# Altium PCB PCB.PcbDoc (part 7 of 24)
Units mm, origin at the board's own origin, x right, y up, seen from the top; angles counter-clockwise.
Board outline 100 x 160 mm, 10 copper layers (TOP_L1, L2, L3, L4, L5, L6, L7, L8, L9, BOTTOM_L10), stack 1.946 mm thick; 1358 components, 1149 nets, 6777 pads, 10914 vias.
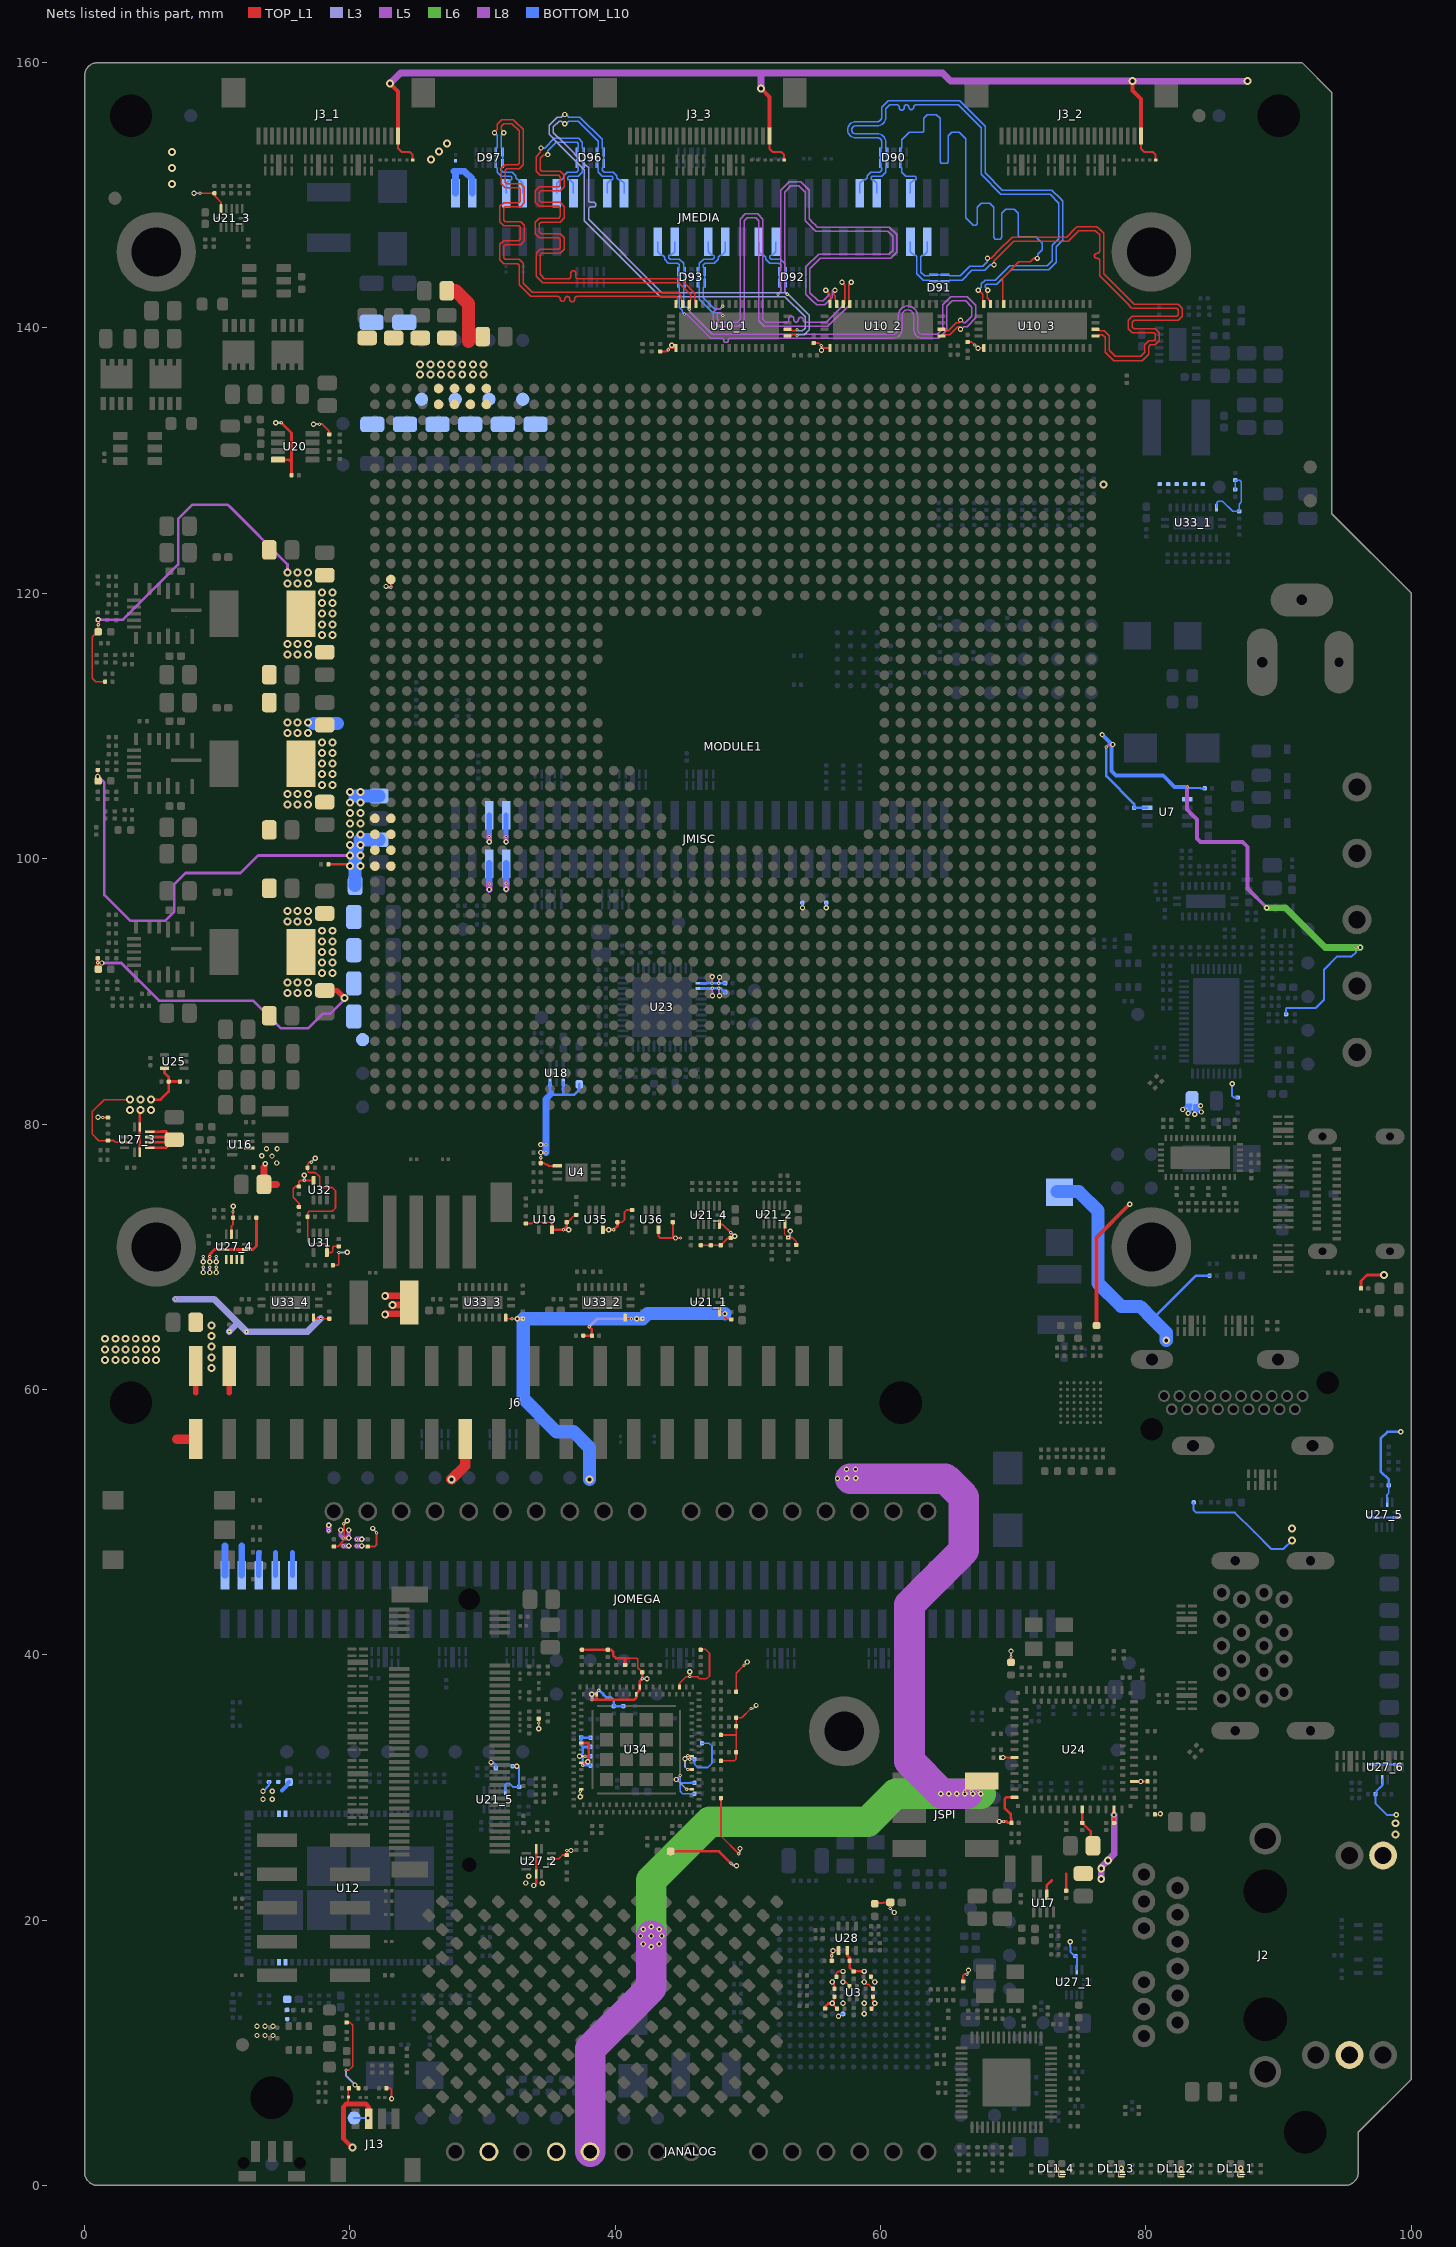
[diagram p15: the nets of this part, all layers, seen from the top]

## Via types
v1: diameter 0.25, hole 0.1, TOP_L1 to L2, tented both sides, 3439 vias
v2: diameter 0.25, hole 0.1, L2 to L3, tented both sides, 2256 vias
v3: diameter 0.25, hole 0.1, L9 to BOTTOM_L10, tented both sides, 1685 vias
v4: diameter 0.25, hole 0.1, L8 to L9, tented both sides, 1675 vias
v5: diameter 0.4, hole 0.2, L3 to L8, tented both sides, 1251 vias
v6: diameter 0.6, hole 0.3, TOP_L1 to BOTTOM_L10, tented both sides, 600 vias
v7: diameter 0.24, hole 0.1, TOP_L1 to L2, tented both sides, 8 vias

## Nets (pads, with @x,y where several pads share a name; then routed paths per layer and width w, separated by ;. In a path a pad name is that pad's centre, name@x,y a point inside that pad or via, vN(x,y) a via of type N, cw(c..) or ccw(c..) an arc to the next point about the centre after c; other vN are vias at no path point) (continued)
+3V3: C38.2 C39.2 C62.2 C69_1.2 C69_2.2 C69_3.2 C80.2 C81.2 C82.2 C83.2 C91.2 C92.1 C93.1 C94.2 C101.2 C115.2 C117.2 C118.2 C122.2 C123.2 C128.2 C129.2 C130.2 C131.2 C132.1 C133.1 C137.2 C140.1 C141.1 C142.1 C143.1 C148.1 C149.1 C174_1.2 C175_2.2 C175_3.2 C175_4.2 C175_5.2 C177.2 C178.2 C179_1.2 C179_2.2 C179_3.2 C179_4.2 C179_5.2 C179_6.2 C202.2 C203.2 C204.2 C206.2 C207.2 C208.2 C228.2 C229.2 C230.2 C231.2 C232.2 C233.2 C234.2 C235.2 C236.2 C237.2 C238.2 C249.2 C250.2 C251.2 C252.2 C258.2 C259.1 C260.2 C262.2 C263.2 C265.2 C266.2 C267.2 C268.2 C269.2 C272.2 C273.2 C274.2 C275.2 C278.2 C300.2 C306.2 C312.2 C313.2 C315.2 C316.2 C317.2 C318.2 C338.2 D15_1.2 D15_2.2 D15_3.2 D85.2 DL1_1.1 DL1_2.1 DL1_3.1 DL1_4.1 J2.14 J2.16 J3_1.22 J3_2.22 J3_3.22 JMEDIA.58 JMEDIA.60 JMISC.53 JMISC.55 JOMEGA.91 JOMEGA.93 JOMEGA.95 L3.2 L4.2 L6.1 L16.1 L18.2 L19.1 MODULE1.A16 MODULE1.A17 MODULE1.A18 MODULE1.A19 MODULE1.B16 MODULE1.B17 MODULE1.B18 MODULE1.B19 MODULE1.B34 MODULE1.E45 MODULE1.E46 MODULE1.F45 MODULE1.F46 MODULE1.G45 MODULE1.G46 MODULE1.H45 MODULE1.H46 R6.2 R7.2 R105.2 R118.1 R124.1 R136.2 R138.2 R155.1 R158.1 R159.1 R160.1 R164.1 R175.1 R176.1 R177.1 R181.2 R191.2 R210.2 R211.2 R220.2 R233.1 R261.2 R275.1 R286.2 R287.2 R295.2 R296.2 R297.2 R298.2 R303.2 R304.2 R317.2 R327.1 R328.1 R329.1 R337.1 R371.2 R372.2 R373.2 R374.2 R375.2 R376.2 R420.1 R431.1 R432.1 R434.1 R435.1 R455.2 R463.1 R464.1 R475.2 R487.2 R489.1 TP74.X TP75.X TP76.X TP77.X TP91.X U3.F7 U3.F9 U3.G6 U3.G7 U3.G9 U3.G10 U3.J6 U3.J7 U3.J9 U3.J10 U3.K7 U3.K9 U4.1 U7.5 U10_1.1 U10_2.1 U10_3.1 U12.4 U12.5 U12.72 U12.73 U16.2 U17.2 U18.4 U18.6 U19.5 U20.4 U21_2.11 U21_3.11 U21_4.11 U21_5.11 U24.A3 U24.A34 U24.A39 U24.A47 U24.A51 U25.5 U27_1.3 U27_2.3 U27_2.6 U27_2.11 U27_3.3 U27_3.6 U27_3.11 U27_4.3 U27_5.3 U27_6.3 U28.4 U28.5 U32.5 U33_1.19 U34.AP18 U34.AP30 U34.AR19 U34.AR31 U34.F2 U34.F34 U34.M2 U34.P34 U34.T2 U34.T34 U34.Y34 U35.5 U36.5 | length 454.3
  TOP_L1 w0.084: U21_2.11@52.789,72.469 52.789,71.69 C175_2.2@53.039,71.44
  TOP_L1 w0.1: R420.1@1.025,117.1 0.991,117.1 0.751,116.86 0.741,116.86 0.572,116.691 0.572,113.597 0.829,113.34 R124.1@1.55,113.34 ; 40.736,39.735 41.619,39.735 41.706,39.647 41.706,39.004 R136.2@42.036,38.674
  TOP_L1 w0.127: C80.2@1,106.69 C80.2@1,106.69 v5(1.002,106.191) v5(1.002,106.191) 1.013,106.18 1.013,105.877 R118.1@1.025,105.865 ; v2(1.377,80.494) R337.1@1.765,80.494 R337.1@1.771,80.5 ; U27_3.3@3.015,78.619 2.341,78.619 2.21,78.75 1.771,78.75 C179_3.2@1.765,78.744 1.079,78.744 0.582,79.241 0.582,80.941 1.479,81.837 v6(3.414,81.837) ; v1(8.7,150.15) C175_3.2@9.786,150.15 9.845,150.091 9.845,149.916 10.286,149.474 U21_3.11@10.286,148.975 ; U27_4.3@11.068,71.686 11.068,72.314 11.193,72.439 C179_4.2@11.193,72.936 v2(11.193,73.385) ; R455.2@16.16,73.75 16.16,74.038 15.722,74.476 15.722,75.13 15.877,75.285 C306.2@16.16,75.285 ; R261.2@18.71,69.35 19.09,69.35 19.164,69.424 v1(19.164,70.312) ; v2(19.709,8.68) 19.729,8.701 19.934,8.701 20.214,8.981 20.214,12.068 20.007,12.275 R317.2@19.75,12.275 ; R489.1@33.266,72.498 33.698,72.498 33.8,72.6 35.13,72.6 35.232,72.499 U19.5@35.232,72.033 ; v1(34.223,34.849) R296.2@34.223,35.175 ; U27_2.3@35.191,24.624 35.75,24.624 36.025,24.899 C179_2.2@36.341,24.899 v1(36.341,25.241) ; C94.2@36.332,72.598 36.413,72.679 36.491,72.679 36.879,73.067 36.981,73.067 R431.1@37.062,73.148 ; v1(37.35,29.7) 37.421,29.771 U34.F34@37.421,29.849 ; C101.2@40.162,72.598 40.509,72.598 40.692,72.781 40.692,73.364 40.841,73.513 R432.1@41.262,73.513 ; U34.AR31@44.841,37.569 44.841,37.844 45.326,38.328 45.596,38.328 v2(45.62,38.353) ; v1(45.375,29.849) U34.F2@45.761,29.849 ; v1(45.453,32.405) 45.453,32.383 45.486,32.349 U34.T2@45.761,32.349 ; v2(45.457,31.343) 45.46,31.346 45.758,31.346 U34.M2@45.761,31.349 ; C231.2@45.614,38.674 45.617,38.671 45.617,38.355 v2(45.62,38.353) ; R210.2@46.436,40.374 46.462,40.4 46.8,40.4 47.1,40.1 47.1,38.4 46.88,38.18 46.352,38.18 46.204,38.328 45.644,38.328 v2(45.62,38.353) ; R329.1@46.45,70.862 R327.1@47.95,70.862 47.956,70.862 48.057,70.963 48.057,70.969 48.487,71.399 48.687,71.399 C175_4.2@48.7,71.412 ; R6.2@47.961,29.199 47.961,26.339 v1(49.3,25) ; R7.2@47.961,31.999 48.988,31.999 49.1,32.111 49.1,32.638 R211.2@49.111,32.649 49.111,33.949 ; R304.2@47.961,33.949 49.111,33.949 ; R297.2@49.111,37.199 49.111,38.611 v1(49.7,39.2) ; v1(50.224,35.942) 49.531,35.249 R286.2@49.111,35.249 R298.2@49.111,34.599 49.111,33.949 ; C175_2.2@53.039,71.44 53.039,71.444 v1(53.043,71.448) ; C175_2.2@53.048,71.448 53.335,71.448 53.639,71.145 R181.2@53.639,70.89 ; C69_2.2@54.951,138.859 55.339,138.859 v1(55.523,138.675) 55.707,138.491 U10_2.1@56.182,138.491 ; v5(56.363,15.329) 56.363,15.311 56.513,15.161 C268.2@56.513,14.829 ; C260.2@56.513,14.229 56.513,13.897 56.363,13.747 v2(56.363,13.729) 56.363,13.696 56.502,13.557 56.502,13.54 C263.2@56.713,13.329 ; C266.2@56.663,15.729 56.663,16.013 56.779,16.129 v2(57.163,16.129) ; v4(57.163,15.329) 57.187,15.305 57.387,15.305 C269.2@57.663,15.029 ; v4(58.763,15.329) 58.93,15.162 59.08,15.162 C273.2@59.413,14.829 ; C275.2@59.263,15.729 59.263,15.629 v2(59.563,15.329) ; C272.2@59.313,13.329 59.313,13.344 59.54,13.57 59.54,13.705 v5(59.563,13.729) 59.563,13.747 59.413,13.897 C262.2@59.413,14.229 ; L6.1@59.563,21.229 59.626,21.292 60.173,21.292 60.21,21.329 C259.1@60.728,21.329 60.728,20.87 v1(60.724,20.866) ; C69_3.2@66.551,138.934 66.875,138.934 v1(67.096,138.713) 67.318,138.491 U10_3.1@67.782,138.491 ; L18.2@69.826,39.424 v1(69.826,39.871)
  TOP_L1 w0.15: C306.2@16.16,75.3 16.16,75.662 16.248,75.75 v1(16.564,75.75) U32.5@17.26,75.75 ; v2(17.7,132.75) 17.707,132.743 17.925,132.743 18.439,132.229 R233.1@18.439,131.974 ; R372.2@18.796,48.15 19.066,48.15 19.543,48.627 v2(19.543,49.863) ; v5(20.387,7.568) 20.41,7.568 20.619,7.359 R375.2@20.641,7.359 ; R371.2@21.336,48.15 21.868,48.15 22,48.282 v2(22,49.2) ; R376.2@22.741,7.324 23.018,7.324 23.135,7.207 23.135,6.538 v1(23.145,6.528) ; J3_1.22@23.624,154.475 23.624,153.557 23.921,153.26 24.524,153.26 24.724,153.06 D15_1.2@24.724,152.66 ; v5(34.382,77.849) v2(34.382,77.449) R220.2@34.382,77.049 34.644,77.049 34.744,76.949 34.871,76.949 34.971,76.849 U4.1@35.632,76.849 ; U36.5@43.262,72.033 43.262,71.532 43.394,71.4 44.342,71.4 ; C69_1.2@43.382,138.236 43.855,138.236 v2(43.983,138.363) 44.11,138.491 U10_1.1@44.582,138.491 ; 44.342,71.396 44.342,71.4 ; C278.2@44.342,72.598 44.342,71.4 ; v1@44.923,71.408 v1(44.919,71.403) 44.915,71.4 44.342,71.4 ; U21_4.11@47.85,72.441 48.075,72.441 v2(48.694,71.822) 48.697,71.819 48.697,71.415 C175_4.2@48.7,71.412 ; J3_3.22@51.624,154.475 51.624,153.498 51.863,153.26 52.524,153.26 52.724,153.06 D15_3.2@52.724,152.66 ; C265.2@56.313,16.929 v2(56.313,17.309) 56.313,17.513 56.509,17.709 U28.4@56.833,17.709 ; R434.1@66.213,15.379 66.213,15.829 66.313,15.929 66.493,15.929 v2(66.51,15.912) ; C204.2@69.066,32.249 69.068,32.25 69.224,32.25 v5(69.225,32.251) v5(69.225,32.251) 70.09,32.25 U24.A34@70.091,32.249 ; U24.A3@79.091,30.449 v5(79.604,30.449) C206.2@80.116,30.449 ; J3_2.22@79.624,154.475 79.624,153.498 79.863,153.26 80.524,153.26 80.724,153.06 D15_2.2@80.724,152.66 ; R191.2@80.666,27.959 81.021,27.959 81.063,28.001 v1(81.09,28.001)
  TOP_L1 w0.18: MODULE1.B34@23.082,121.036 23.1,121.018 v1(23.1,120.45) ; U24.A47@75.191,28.349 75.191,27.924 75.189,27.922 75.189,27.389 75.191,27.387 C207.2@75.191,27.324 75.818,26.698 75.829,26.698 75.829,25.771 C208.2@76.003,25.597
  TOP_L1 w0.2: C91.2@1,117.99 1.025,117.965 v2(1.025,117.621) R420.1@1.025,117.1 ; U27_3.6@4.165,77.869 U27_3.11@4.165,79.769 4.165,81.067 v6(4.214,81.067) ; v6(5.014,81.837) 5.737,81.837 6.34,82.44 C338.2@6.34,83.202 ; U25.5@6.025,84.202 6.025,83.852 6.34,83.537 C338.2@6.34,83.202 ; R487.2@7.19,83.202 C338.2@6.34,83.202 ; U20.4@14.574,130.074 15.369,130.074 15.599,129.844 ; v1(14.824,132.85) 15.599,132.075 15.599,129.844 ; C300.2@15.599,128.899 15.599,129.844 ; C251.2@18.375,99.566 19.699,99.566 cw(c19.699,99.123) v6(20.012,99.436) ; 34.041,22.793 U27_2.11@34.041,23.474 U27_2.6@34.041,25.374 ; U19.5@35.232,72.033 v2(36.097,72.033) 36.332,72.267 C94.2@36.332,72.598 ; U34.P34@37.421,31.849 37.84,31.849 37.919,31.928 v1(37.933,31.928) 37.933,31.942 38,32.009 38,32.349 ; U34.T34@37.421,32.349 v2(37.711,32.349) 38,32.349 ; U34.Y34@37.421,33.349 38,33.349 38,32.349 ; R295.2@37.486,40.374 R287.2@39.436,40.374 39.675,40.374 39.844,40.205 39.844,39.948 40.057,39.735 40.736,39.735 R303.2@40.736,39.224 ; v1(38.241,36.595) 38.541,36.595 ; U34.AP30@38.591,37.019 38.591,36.646 38.541,36.595 ; U35.5@39.062,72.033 v2(39.873,72.033) 40.162,72.322 C101.2@40.162,72.598 ; U34.AP18@41.591,37.019 41.591,36.771 41.416,36.595 38.541,36.595 ; U34.AP18@41.591,37.094 41.841,37.344 U34.AR19@41.841,37.569 41.841,37.996 v1(42.036,38.191) R136.2@42.036,38.674 ; L19.1@44.173,25.175 47.823,25.175 v2(48.726,24.272) ; R435.1@55.813,13.329 55.813,13.474 56.068,13.729 v2(56.363,13.729) ; U28.5@57.483,17.709 57.483,17.326 57.663,17.146 C274.2@57.663,16.929 57.663,16.429 C267.2@57.963,16.129 v5(58.763,16.129) ; v1(69.278,27.436) 69.287,27.426 69.499,27.426 69.601,27.324 69.801,27.324 69.856,27.379 69.856,27.665 69.797,27.724 69.797,28.007 69.341,28.463 69.341,29.132 69.459,29.249 U24.A39@70.091,29.249 ; U17.2@72.531,21.909 72.531,22.631 72.9,23 ; v5(73.25,1.264) 73.25,1.257 73.645,0.862 DL1_4.1@73.645,0.855 ; C123.2@73.981,22.209 73.981,23.5 ; C202.2@77.591,27.324 v5(77.591,27.924) U24.A51@77.591,28.349 ; v2(78.147,0.855) v2(78.147,0.855) ; v2(82.645,0.844) DL1_2.1@82.645,0.855 ; v2(87.14,0.855) DL1_1.1@87.145,0.855 ; R105.2@96.201,67.609 96.201,68.151 96.664,68.614 v6(97.921,68.614)
  TOP_L1 w0.3: v6(23.026,158.424) 23.624,157.826 J3_1.22@23.624,154.475 ; v6(50.975,158.041) 51.002,158.041 51.624,157.418 J3_3.22@51.624,154.475 ; L16.1@76.275,64.81 76.275,71.458 v5(78.768,73.952) ; v6(78.981,158.609) 78.981,157.889 79.624,157.245 J3_2.22@79.624,154.475
  TOP_L1 w0.5: C117.2@13.518,75.441 13.518,76.75 ; C117.2@13.519,75.44 14.461,75.44
  TOP_L1 w1: C177.2@27.3,142.8 27.96,142.8 28.936,141.824 28.936,138.988
  L5 w0.5: v6(23.026,158.424) 23.815,159.212 50.984,159.212 ; v6(50.975,158.041) 50.984,158.051 50.984,159.212 ; v6(76.626,23.1) v6(76.626,23.9) 76.646,23.919 76.646,24.019 v6(77.126,24.5) 77.6,24.973 77.6,27.915 v5(77.591,27.924) ; v6(87.65,158.597) 87.644,158.603 78.986,158.603 v6(78.981,158.609) 65.271,158.609 64.667,159.212 50.984,159.212
  L6 w0.5: v5(89.1,96.3) 90.511,96.3 93.511,93.3 v5(96.15,93.3)
  L3 w0.127: v5(1.01,80.5) 1.013,80.497 1.374,80.497 v2(1.377,80.494) ; v5(8.25,150.15) v1(8.7,150.15) ; v2(11.193,73.385) 11.196,73.388 11.196,73.788 v5(11.199,73.791) ; v5(34.223,34.423) v1(34.223,34.849) ; v1(36.341,25.241) v5(36.659,25.241) ; v5(37.348,29.305) 37.35,29.308 v1(37.35,29.7) ; v5(44.6,30.6) 44.612,30.6 45.363,29.849 v1(45.375,29.849) ; v1(45.453,32.405) 45.453,32.384 45.259,32.19 v5(45.259,32.169) 45.259,31.541 v2(45.457,31.343) ; v2(45.62,38.353) v5(45.62,38.72) ; v1(49.3,25) 49.3,25.033 49.395,25.128 v5(49.395,25.391) ; v1(49.7,39.2) 49.95,39.45 v5(49.954,39.45) ; v1(50.224,35.942) 50.375,35.942 v5(50.611,36.178) ; v1(53.043,71.448) 53.043,71.482 53.178,71.616 v5(53.178,71.929) ; v1(55.523,138.675) 55.532,138.666 55.532,138.335 v5(55.542,138.326) ; v1(60.724,20.866) 61.02,20.57 v5(61.032,20.57) ; v1(67.096,138.713) 67.334,138.475 v5(67.334,138.469) ; v1(69.826,39.871) v5(69.826,40.274)
  L3 w0.15: v1(16.564,75.75) v5(16.564,76.142) ; v5(17.25,132.75) v2(17.7,132.75) ; v1(19.164,70.312) 19.168,70.308 19.772,70.308 v5(19.786,70.323) ; v2(19.543,49.863) 19.553,49.863 19.79,50.1 v5(19.8,50.1) ; v2(19.709,8.68) 19.709,8.246 v5(20.387,7.568) ; v5(21.719,49.519) 21.719,49.5 22,49.219 v2(22,49.2) ; v2(34.382,77.449) v5(34.382,77.849) ; v2(43.983,138.363) 43.983,138.39 44.256,138.663 v5(44.256,138.706) ; v5(44.54,71.412) 44.544,71.408 44.914,71.408 v1(44.919,71.403) ; v2(48.694,71.822) 48.708,71.822 48.99,71.54 v5(49.004,71.54) ; v2(56.313,17.309) 56.323,17.319 56.323,17.534 56.409,17.62 v5(56.409,17.688) ; v2(66.51,15.912) 66.51,15.939 66.574,16.003 66.574,16.181 v5(66.622,16.229) ; v5(81.086,28.003) 81.088,28.001 v1(81.09,28.001)
  L3 w0.18: v5(22.718,120.518) 22.764,120.518 22.832,120.45 v1(23.1,120.45)
  L3 w0.2: v5(1.023,118.019) 1.025,118.017 v2(1.025,117.621) ; v5(14.419,132.85) v1(14.824,132.85) ; v2(36.097,72.033) 36.099,72.032 36.486,72.032 v5(36.487,72.031) ; v4(37.307,32.349) v2(37.711,32.349) ; v1(37.933,31.928) v5(37.933,31.935) ; v5(38.233,37.018) 38.241,37.01 v1(38.241,36.595) ; v5(39.508,72.033) v2(39.873,72.033) ; v1(42.036,38.191) 42.037,38.19 v5(42.393,38.189) v5(42.393,38.189) ; v2(48.726,24.272) 48.74,24.272 48.878,24.134 49.102,24.134 v5(49.141,24.095) ; v5(68.936,27.427) 68.94,27.431 69.273,27.431 v1(69.278,27.436) ; v2(78.147,0.855) v5(78.147,1.287) ; v2(82.645,0.844) v5(82.645,1.266) ; v2(87.14,0.855) v5(87.14,1.3)
  L8 w0.127: v5(44.6,30.6) v4(44.9,30.9) ; v5(45.259,32.169) 45.277,32.151 45.59,32.151 v4(45.608,32.132) ; v4(95.833,93.321) 95.843,93.31 96.14,93.31 v5(96.15,93.3)
  L8 w0.15: v5(34.382,77.849) 34.762,77.849 v4(34.773,77.838) ; v5(34.382,78.449) 34.762,78.449 v3(34.773,78.438)
  L8 w0.2: v5(1.002,106.191) 1.029,106.191 1.489,105.73 1.489,97.264 3.43,95.323 6.088,95.323 6.755,95.99 6.755,98.06 7.608,98.914 11.745,98.914 13.068,100.236 v6(20.012,100.236) ; v5(1.023,118.019) 2.901,118.019 7.055,122.173 7.055,125.588 8.151,126.684 10.784,126.684 11.055,126.414 15.289,122.18 v6(15.289,121.554) ; v4(37.553,31.664) 37.785,31.897 37.895,31.897 v5(37.933,31.935) ; v5(38.233,37.018) 38.271,37.056 38.496,37.056 v4(38.763,37.323)
  L8 w0.3: v5(19.3,49.4) 19.3,49 v4(19.5,48.8) ; v5(19.9,48.8) v5(19.9,49.4) ; v3(83.103,105.4) 83.103,103.695 83.848,102.95 83.848,101.518 84.111,101.255 87.28,101.255 87.638,100.897 87.638,97.762 v5(89.1,96.3)
  L8 w0.4: v4(18.395,49.348) v5(18.395,49.748) ; v4(19.5,48.2) v5(19.9,48.2) ; v4(19.5,48.8) v5(19.9,48.8) ; v4(20.5,48.2) v5(20.9,48.2) ; v4(20.5,48.7) v5(20.9,48.7)
  L8 w0.5: v5(30.499,97.672) v4(30.499,98.091) ; v5(31.769,97.683) v4(31.769,98.134)
  BOTTOM_L10 w0.109: v5(54.109,96.3) R373.2@54.109,96.678 ; v5(55.899,96.3) R374.2@55.899,96.678
  BOTTOM_L10 w0.127: v4(44.9,30.9) 44.9,30.3 ; v4(45.608,32.132) C234.2@45.98,32.132 45.98,31.72 46.2,31.5 46.967,31.5 47.284,31.817 47.284,33.116 47.068,33.332 R138.2@46.53,33.332 ; C232.2@45.98,29.532 45.068,29.532 44.9,29.7 44.9,30.3 ; C233.2@45.98,30.332 44.932,30.332 44.9,30.3 ; U33_1.19@85.325,126.45 85.325,126.835 85.437,126.946 85.76,126.946 86.531,126.175 R155.1@87.025,126.175 87.025,126.715 87.188,126.878 87.188,128.412 87.075,128.525 C174_1.2@86.725,128.525 R158.1@86.725,127.825 ; U27_5.3@98.171,51.496 98.171,52.055 98.298,52.182 C179_5.2@98.298,52.771
  BOTTOM_L10 w0.15: v5(13.453,29.704) 13.9,30.151 C130.2@13.9,30.41 ; TP91.X@20.32,5.08 v5(21.36,5.08) ; v4(30.635,31.882) 30.654,31.863 30.837,31.863 31,31.7 R463.1@31,31.445 ; U21_5.11@31.7,29.77 31.7,30.173 31.832,30.305 32.018,30.305 32.278,30.045 C175_5.2@32.75,30.045 32.75,31.463 32.739,31.463 32.607,31.595 v3@32.573,31.595 ; R464.1@32.25,31.595 32.254,31.599 32.569,31.599 v5(32.573,31.602) ; v3(56.827,12.755) 56.846,12.774 56.941,12.774 57.095,12.929 U3.G10@57.163,12.929 ; v5(74.287,18.368) 74.287,18.037 74.301,18.023 74.301,17.663 74.298,17.66 74.298,17.622 C179_1.2@74.626,17.293 ; C179_1.2@74.681,17.293 74.781,17.193 U27_1.3@74.781,16.259 ; v3(83.103,105.4) 83.13,105.4 83.222,105.308 84.117,105.308 84.126,105.3 C62.2@84.428,105.3 ; v4(86.5,83.034) 86.5,82.123 86.626,81.997 R475.2@86.903,81.997 ; R275.1@90.553,88.272 90.553,88.334 90.535,88.352 90.535,88.654 90.623,88.741 92.795,88.741 93.418,89.364 93.418,91.638 94.393,92.614 95.485,92.614 95.833,92.961 v4(95.833,93.321) ; U27_6.3@97.815,30.585 97.815,30.143 97.367,29.695 97.367,29.577 C179_6.2@97.29,29.5 97.29,28.8 98.162,27.928 v3(98.856,27.928)
  BOTTOM_L10 w0.2: U18.6@35.075,83.131 35.075,82.376 35.174,82.276 35.25,82.2 36.075,82.2 36.9,82.2 37.268,82.568 37.275,82.568 C137.2@37.275,82.996 ; 36.075,82.201 U18.4@36.075,83.131 ; v4(37.307,32.349) v3@37.311,32.349 ; C230.2@37.553,33.749 C237.2@38.121,33.749 ; C230.2@37.553,33.755 C230.2@37.42,33.755 37.42,33.181 37.553,33.049 ; C236.2@38.121,31.649 38.114,31.657 37.56,31.657 v4(37.553,31.664) 37.553,32.339 ; C235.2@38.121,32.349 37.563,32.349 37.553,32.339 ; C238.2@38.121,33.049 37.553,33.049 ; v4(38.763,37.323) 39.291,36.795 39.641,36.795 39.891,36.545 C229.2@39.891,36.119 C228.2@40.591,36.119 ; v3@86.5,83.044 v3@86.503,83.047 ; C179_5.2@98.298,52.771 98.298,53.192 97.69,53.8 97.69,56.3 98.19,56.8 v5(99.19,56.8) ; v3@37.311,32.349 37.311,32.353 37.553,32.595 37.553,33.049 ; v3@37.311,32.349 37.542,32.349 37.553,32.339
  BOTTOM_L10 w0.3: 14.879,29.748 15.26,30.129 15.26,30.27 C132.1@15.4,30.41 ; v4(76.69,109.35) 77.411,108.629 77.411,106.589 77.75,106.25 81.3,106.25 82.15,105.4 v3(83.103,105.4) U7.5@83.103,104.478
  BOTTOM_L10 w0.4: JOMEGA.95@13.126,46 13.126,47.697 ; JOMEGA.93@14.396,46 14.396,47.697 ; JOMEGA.91@15.666,46 15.666,47.697
  BOTTOM_L10 w0.5: JMEDIA.60@27.959,150.141 27.959,151.667 27.826,151.8 28.643,151.8 29.229,151.214 JMEDIA.58@29.229,150.141 ; v4(30.499,98.091) JMISC.55@30.499,99.629 ; v4(31.769,98.134) JMISC.53@31.769,99.629 ; v4(34.773,77.838) 34.773,81.874 35.174,82.276
  BOTTOM_L10 w1: 17.25,110.178 19.039,110.178 ; C252.2@20.389,97.978 20.389,100.412 cw(c20.938,100.412) 20.55,100.8 ; 20.4,104.728 C249.2@22.189,104.728 ; 20.782,101.428 C250.2@22.189,101.428
  other v1: 82.645,0.844 78.147,0.855 87.14,0.855 73.25,1.264 20.387,7.568 19.709,8.68 56.363,13.729 59.563,13.729 56.363,15.329 57.163,15.329 58.763,15.329 59.563,15.329 66.51,15.912 57.163,16.129 58.763,16.129 56.313,17.309 33.864,22.609 34.491,22.763 33.243,22.795 33.483,23.3 48.726,24.272 77.591,27.924 79.604,30.449 45.457,31.343 69.225,32.251 37.711,32.349 45.62,38.353 22,49.2 19.543,49.863 48.694,71.822 36.097,72.033 39.873,72.033 11.193,73.385 78.768,73.952 13.626,77.012 14.489,77.062 34.382,77.449 14.126,77.581 13.357,77.601 13.71,78.137 14.51,78.137 1.377,80.494 1.002,106.191 1.025,117.621 17.7,132.75 43.983,138.363
  other v2: 73.25,1.264 23.14,6.533 20.387,7.568 59.563,13.729 56.363,15.329 57.163,15.329 58.763,15.329 58.763,16.129 60.724,20.866 33.864,22.609 34.491,22.763 33.243,22.795 33.483,23.3 49.3,25 36.341,25.241 69.278,27.436 77.591,27.924 81.09,28.001 37.35,29.7 45.375,29.849 79.604,30.449 37.933,31.928 69.225,32.251 45.453,32.405 34.223,34.849 50.224,35.942 38.241,36.595 42.036,38.191 49.7,39.2 69.826,39.871 19.164,70.312 44.919,71.403 53.043,71.448 78.768,73.952 16.564,75.75 13.626,77.012 14.489,77.062 14.126,77.581 13.357,77.601 13.71,78.137 14.51,78.137 1.002,106.191 23.1,120.45 14.824,132.85 55.523,138.675 67.096,138.713 8.7,150.15
  other v3: 21.36,5.08 13,11.3 13.6,11.3 14.2,11.3 13,12 13.6,12 14.2,12 58.763,12.929 56.363,13.729 57.163,13.729 58.763,13.729 59.563,13.729 56.363,15.329 57.163,15.329 58.763,15.329 59.563,15.329 57.163,16.129 58.763,16.129 74.287,18.368 13.453,29.104 14.153,29.104 13.453,29.704 14.153,29.704 44.9,30.9 32.573,31.602 37.553,31.664 30.635,31.882 45.608,32.132 37.307,32.349 38.763,37.323 19.5,48.2 20.5,48.2 20.5,48.7 19.5,48.8 18.395,49.348 99.19,56.8 34.773,77.838 86.5,83.034 95.833,93.321 54.109,96.3 55.899,96.3 30.499,98.091 31.769,98.134 76.69,109.35
  other v4: 21.36,5.08 13,11.3 13.6,11.3 14.2,11.3 13,12 13.6,12 14.2,12 56.827,12.755 58.763,12.929 56.363,13.729 57.163,13.729 58.763,13.729 59.563,13.729 56.363,15.329 59.563,15.329 57.163,16.129 58.763,16.129 74.287,18.368 98.856,27.928 13.453,29.104 14.153,29.104 13.453,29.704 14.153,29.704 32.573,31.602 99.19,56.8 34.773,78.438 54.109,96.3 55.899,96.3 83.103,105.4
  other v5: 23.14,6.533 13,11.3 13.6,11.3 14.2,11.3 13,12 13.6,12 14.2,12 56.827,12.755 58.763,12.929 56.363,13.729 57.163,13.729 58.763,13.729 57.163,15.329 58.763,15.329 59.563,15.329 57.163,16.129 33.864,22.609 34.491,22.763 33.243,22.795 33.483,23.3 98.856,27.928 13.453,29.104 14.153,29.104 14.153,29.704 30.635,31.882 37.307,32.349 13.626,77.012 14.489,77.062 14.126,77.581 13.357,77.601 13.71,78.137 14.51,78.137 86.5,83.034 76.69,109.35
  other v6: 3.414,81.067 5.014,81.067 4.214,81.837 20.782,99.436 20.782,100.236 20.012,101.036 20.782,101.036 20.012,101.836 20.782,101.836 20.012,102.636 20.782,102.636 20.012,103.436 20.782,103.436 15.289,104.076 16.059,104.076 16.829,104.076 20.012,104.236 20.782,104.236 15.289,104.876 16.059,104.876 16.829,104.876 20.012,105.036 20.782,105.036 17.9,105.565 18.67,105.565 17.9,106.365 18.67,106.365 17.9,107.165 18.67,107.165 17.9,107.965 18.67,107.965 17.9,108.765 18.67,108.765 15.289,109.454 16.059,109.454 16.829,109.454 15.289,110.254 16.059,110.254 16.829,110.254 15.289,115.376 16.059,115.376 16.829,115.376 15.289,116.176 16.059,116.176 16.829,116.176 17.9,116.865 18.67,116.865 17.9,117.665 18.67,117.665 17.9,118.465 18.67,118.465 17.9,119.265 18.67,119.265 17.9,120.065 18.67,120.065 15.289,120.754 16.059,120.754 16.829,120.754 16.059,121.554 16.829,121.554 76.801,128.183 25.265,136.474 26.065,136.474 26.865,136.474 27.665,136.474 28.465,136.474 29.265,136.474 30.065,136.474 25.265,137.244 26.065,137.244 26.865,137.244 27.665,137.244 28.465,137.244 29.265,137.244 30.065,137.244 6.584,150.845 6.584,152.045 26.126,152.7 6.584,153.245 26.726,153.3 27.326,153.9
+3V3_LIMITED: C174_2.2 C174_3.2 C174_4.2 C175_1.2 C222.2 C271.2 D82.2 J6.1 J6.17 J13.2 JANALOG.2 JANALOG.4 R122.1 R169.1 R170.1 R171.1 U21_1.11 U27_3.7 U27_3.8 U27_3.9 U27_3.10 U33_2.19 U33_3.19 U33_4.19 | length 75.8
  TOP_L1 w0.1: D82.2@19.865,6.669 C271.2@19.865,7.294
  TOP_L1 w0.127: U33_4.19@17.25,65.4 17.25,65.382 17.306,65.325 C174_4.2@18.45,65.325 ; U33_3.19@31.75,65.4 31.75,65.382 31.806,65.325 v1(32.216,65.325) C174_3.2@32.95,65.325 ; U33_2.19@40.75,65.4 40.75,65.382 40.806,65.325 41.95,65.325 v2(41.216,65.325) ; U21_1.11@47.85,65.85 48.113,65.85 v2(48.262,65.701) 48.262,65.402 48.389,65.275 48.661,65.275 C175_1.2@48.689,65.303
  TOP_L1 w0.15: 19.722,6.141 19.865,6.284 D82.2@19.865,6.669
  TOP_L1 w0.2: U27_3.7@4.915,78.219 5.748,78.219 5.766,78.201 6.147,78.201 C222.2@6.765,78.819 6.565,78.619 U27_3.8@4.915,78.619 ; U27_3.9@4.915,79.019 6.565,79.019 6.147,79.437 5.766,79.437 5.748,79.419 U27_3.10@4.915,79.419 ; v1(10.906,64.361) 10.91,64.357 R170.1@10.91,64.35 ; R171.1@37.585,64.05 R122.1@38.235,64.05 38.235,64.5 v1(38.028,64.707)
  TOP_L1 w0.35: v6(20.191,2.85) 19.517,3.524 19.517,5.936 19.722,6.141 21.176,6.141 21.417,5.899 J13.2@21.417,5.024
  TOP_L1 w0.7: 6.955,56.25 J6.1@8.37,56.25
  TOP_L1 w0.8: v6(27.655,53.214) 28.69,54.248 J6.17@28.69,56.25
  L3 w0.127: v2@12.208,64.348 v1(12.21,64.35) ; v1(32.216,65.325) 32.216,65.332 v5(32.607,65.332) ; v2(41.216,65.325) 41.216,65.332 v5(41.607,65.332)
  L3 w0.2: v1(38.028,64.707) 38.646,65.325 v2(41.216,65.325)
  L3 w0.5: v2(6.845,66.804) 9.752,66.804 12.208,64.348 16.804,64.348 v2(17.793,65.337) ; v1(10.906,64.361) 11.534,64.988 11.534,64.991
  L8 w0.127: v5(32.607,65.332) 33.06,65.332 v4(33.06,65.327) ; v5(41.607,65.332) 42.06,65.332 v3(42.06,65.327)
  BOTTOM_L10 w1: v6(38.055,53.214) 38.055,55.614 36.855,56.814 35.565,56.814 33.06,59.319 v4(33.06,65.327) v3(42.06,65.327) 42.447,65.714 48.249,65.714 v2(48.262,65.701)
  other v1: 17.793,65.337 41.216,65.325 48.262,65.701 6.845,66.804
  other v2: 12.21,64.35 10.906,64.361 38.028,64.707 32.216,65.325
  other v3: 33.06,65.327 48.262,65.701
  other v4: 42.06,65.327 48.262,65.701
  other v5: 48.262,65.701
  other v6: 1.545,62.214 2.315,62.214 3.085,62.214 3.855,62.214 4.625,62.214 5.395,62.214 1.545,63.014 2.315,63.014 3.085,63.014 3.855,63.014 4.625,63.014 5.395,63.014 1.545,63.814 2.315,63.814 3.085,63.814 3.855,63.814 4.625,63.814 5.395,63.814
+5V: C61.2 C102.2 C103.2 C104.2 C165.2 C166.2 C223.2 C276.2 C305.2 C334.1 C335.1 C336.1 C337.1 D3.A F1.1 JMISC.54 JMISC.56 JOMEGA.97 JOMEGA.99 L5.2 R129.1 R263.2 R276.2 R336.1 R456.2 R492.2 R495.2 TP83.X U7.3 U23.14 U23.15 U27_4.6 U27_4.11 U27_5.6 U27_5.11 U27_6.6 U27_6.11 U31.5 | length 110.9
  TOP_L1 w0.127: v1(17.088,77.116) 16.944,77.116 16.815,76.987 16.81,76.987 R263.2@16.81,76.71 16.81,76.418 16.885,76.344 17.391,76.344 17.715,76.019 17.715,75.294 17.79,75.22 18.66,75.22 18.91,74.97 18.91,73.67 18.66,73.42 16.935,73.42 16.81,73.295 R456.2@16.81,73.02 16.81,71.17 17.01,70.97 18.11,70.97 18.26,70.82 U31.5@18.26,70.31 18.636,70.31 18.71,70.384 18.71,70.701 18.785,70.775 C305.2@19.16,70.775
  TOP_L1 w0.2: C102.2@1,92.491 v1(1,92.147) 1,91.691 R129.1@1.025,91.666 ; 9.433,69.808 v1(9.433,70.008) 9.433,70.18 9.789,70.536 U27_4.6@10.318,70.536 U27_4.11@12.218,70.536 12.68,70.536 12.955,70.812 R336.1@12.955,72.923
  TOP_L1 w0.4: C104.2@18.1,90.066 19.019,90.066 v6(19.59,89.495)
  TOP_L1 w0.5: v6(22.66,65.65) 22.699,65.689 24.221,65.689 F1.1@24.34,65.57 ; v6(22.66,67.05) F1.1@24.46,67.05 ; v6(23.211,66.358) 24.352,66.358 F1.1@24.46,66.25
  L3 w0.127: v1(17.088,77.116) v5(17.388,77.416)
  L3 w0.2: v1(1,92.147) 1.005,92.142 1.3,92.142 v5(1.306,92.137) ; v5(8.933,68.808) v1(8.933,69.208) ; v5(8.933,69.608) v1(8.933,70.008) ; v5(9.433,68.808) v2(9.433,69.208) ; v5(9.433,69.608) v1(9.433,70.008) ; v5(9.933,68.808) v2(9.933,69.208) ; v5(9.933,69.608) v1(9.933,70.008)
  L8 w0.127: v3(47.295,90.608) 47.305,90.619 47.305,91.1 v5(47.316,91.111) ; v4(47.297,90.23) 47.31,90.217 47.31,89.689 v5(47.323,89.676) ; v3(47.795,90.608) 47.818,90.632 47.818,91.037 v5(47.85,91.069) ; v3(47.797,90.23) 47.82,90.207 47.82,89.702 v5(47.859,89.663)
  L8 w0.2: v5(1.306,92.137) 2.763,92.137 5.608,89.292 8.892,89.292 8.9,89.3 12.7,89.3 14.774,87.226 16.868,87.226 17.942,88.3 18.5,88.3 19.59,89.39 v6(19.59,89.495) ; v3(77.011,108.411) 77.2,108.6 v5(77.5,108.6)
  L8 w0.4: v5(30.499,101.269) v3(30.499,101.669) ; v5(31.769,101.269) v4(31.769,101.669)
  BOTTOM_L10 w0.15: R495.2@83.595,51.475 83.595,50.891 83.771,50.715 86.705,50.715 88.145,49.275 88.145,49.251 89.421,47.975 90.365,47.975 v6(90.99,48.6) ; U27_5.11@97.021,50.346 U27_5.6@98.921,50.346 ; U27_6.6@97.065,31.735 U27_6.11@98.965,31.735
  BOTTOM_L10 w0.2: U23.14@46.473,90.616 C165.2@48.288,90.616 ; U23.15@46.483,90.216 47.282,90.216 v4(47.297,90.23) v3(47.797,90.23) 47.974,90.23 C166.2@48.288,89.916 ; v3(77.011,108.411) 77.011,106.212 79.103,104.119 C61.2@79.103,103.828 U7.3@80.103,103.828 ; 80.5,65.3 83.775,68.575 R492.2@84.795,68.575 ; v4(82.763,81.095) 83.115,81.447 R276.2@83.403,81.447
  BOTTOM_L10 w0.3: v5(83.172,80.803) 83.281,80.912 83.281,81.325 R276.2@83.303,81.347 ; v3(83.674,80.723) 83.674,81.248 83.703,81.277 84.078,80.902 v4(84.177,80.902) ; R276.2@83.703,81.347 83.729,81.373 v5(84.114,81.373)
  BOTTOM_L10 w0.4: v3(30.499,101.669) JMISC.56@30.499,103.277 ; v4(31.769,101.669) JMISC.54@31.769,103.277
  BOTTOM_L10 w0.5: JOMEGA.99@10.586,46 10.586,48.22 ; JOMEGA.97@11.856,46 11.856,48.22
  BOTTOM_L10 w1: D3.A@73.305,74.911 74.926,74.911 76.382,73.455 76.382,67.986 78.12,66.248 79.552,66.248 80.5,65.3 81.526,64.274 v6(81.526,63.7)
  other v1: 9.433,69.208 9.933,69.208
  other v2: 8.933,69.208 8.933,70.008 9.433,70.008 9.933,70.008 17.088,77.116 1,92.147
  other v3: 83.172,80.803 84.177,80.902 82.763,81.095 84.114,81.373 47.297,90.23 31.769,101.669
  other v4: 83.674,80.723 83.172,80.803 84.114,81.373 47.797,90.23 47.295,90.608 47.795,90.608 30.499,101.669 77.011,108.411
  other v5: 83.674,80.723 84.177,80.902 82.763,81.095
  other v6: 98.8,26.447 98.8,27.297 90.99,49.5 15.289,89.877 16.059,89.877 16.829,89.877 15.289,90.677 16.059,90.677 16.829,90.677 17.9,91.366 18.67,91.366 17.9,92.166 18.67,92.166 17.9,92.966 18.67,92.966 17.9,93.766 18.67,93.766 17.9,94.566 18.67,94.566 15.289,95.255 16.059,95.255 16.829,95.255 15.289,96.055 16.059,96.055 16.829,96.055
+5V_LIMITED: C221.2 J6.2 J6.4 JANALOG.5 JSPI.2 U27_4.7 U27_4.8 U27_4.9 U27_4.10 | length 92.9
  TOP_L1 w0.2: v2(66.334,29.719) JSPI.2@66.8,30.184 ; v1(66.834,29.719) JSPI.2@66.834,30.15 ; v1(67.334,29.719) 67.334,30.187 JSPI.2@67.627,30.48
  TOP_L1 w0.4: 8.37,59.75 J6.2@8.37,61.75 ; 10.91,59.75 J6.4@10.91,61.75
  L5 w2.3: JANALOG.5@38.1,2.54 38.1,10.285 42.702,14.887 v5(42.702,17.999) v5(42.702,18.799) ; 57.694,53.275 64.881,53.275 66.274,51.882 66.274,47.874 62.175,43.775 62.175,31.983 64.639,29.519 65.034,29.519 65.534,29.519 66.034,29.519 66.534,29.519
  L6 w2.3: v5(42.702,18.799) v5(42.702,19.499) 42.702,23.001 47.121,27.419 59.034,27.419 61.134,29.519 65.034,29.519 65.534,29.519 66.034,29.519 66.534,29.519 67.034,29.519 v5(67.534,29.519)
  L3 w0.2: v2(66.334,29.719) 66.534,29.519 ; v1(66.834,29.719) v5@67.034,29.519 ; v1(67.334,29.719) v5(67.534,29.519)
  other v1: 66.334,29.719
  other v2: 66.834,29.719 67.334,29.719
  other v5: 42.102,18.199 43.302,18.199 41.902,18.799 43.502,18.799 42.102,19.299 43.302,19.299 64.534,29.519 65.134,29.519 65.734,29.519 66.334,29.519 66.934,29.519 56.752,53.278 57.436,53.289 58.119,53.3 57.425,53.972 58.108,53.983
  other v6: 9.555,61.614 9.555,62.414 9.555,63.214 9.555,64.014 9.555,64.814
A_CLK_1_N: D96.2 D96.9 JMEDIA.42 U10_1.18 | length 41
  TOP_L1 w0.109: U10_1.18@52.982,139.391 53.053,139.461 53.296,139.461 53.323,139.488 53.585,139.488 53.622,139.488 v1(53.695,139.416)
  L3 w0.104: v3(36.2,155.391) 36.128,155.391 35.93,155.588 35.758,155.588 35.316,155.147 35.316,154.727 35.985,154.058 37.805,152.238 37.984,152.059 37.984,151.6 37.984,149.653 ccw(c38.163,149.653) 38.163,149.473 38.367,149.473 cw(c38.367,149.294) 38.367,149.115 38.163,149.115 ccw(c38.163,148.936) 37.984,148.936 37.984,148.526 37.984,148.19 43.504,142.67 52.906,142.67 54.609,140.966 54.609,139.867 54.23,139.488 53.806,139.488 53.734,139.416 v1(53.695,139.416)
  BOTTOM_L10 w0.109: v3(36.2,155.391) 36.276,155.391 36.473,155.588 37.21,155.588 38.717,154.082 38.717,153.589 38.619,153.492 38.619,152.142 38.717,152.044 38.717,151.752 39.031,151.437 39.724,151.437 39.82,151.341 39.82,151.206 39.776,151.161 39.659,151.161 39.389,150.891 JMEDIA.42@39.389,150.141
  other v2: 53.695,139.416
  other v4: 36.2,155.391
  other v5: 36.2,155.391
A_CLK_1_P: D96.1 D96.10 JMEDIA.40 U10_1.19 | length 41
  TOP_L1 w0.109: U10_1.19@52.982,139.891 53.053,139.82 53.296,139.82 ; v1@53.604,139.793 53.459,139.793 ; v2(53.695,139.865) 53.622,139.793 53.585,139.793 53.459,139.793 ; 53.296,139.82 53.323,139.793 ; 53.296,139.82 53.323,139.793 ; 53.323,139.793 53.459,139.793 ; 53.323,139.793 53.459,139.793
  L3 w0.104: v3(36.2,156.091) 36.128,156.091 35.93,155.893 35.631,155.893 35.011,155.273 35.011,154.601 35.68,153.932 37.679,151.933 37.679,148.063 43.378,142.365 52.78,142.365 54.304,140.84 54.304,139.993 54.104,139.793 53.806,139.793 53.734,139.865 v2(53.695,139.865)
  BOTTOM_L10 w0.109: v3(36.2,156.091) 36.276,156.091 36.473,155.893 37.336,155.893 39.021,154.208 39.021,153.589 39.119,153.492 D96.1@39.119,152.379 39.119,152.142 39.021,152.044 39.021,151.878 39.157,151.742 39.85,151.742 40.125,151.468 40.125,151.308 40.272,151.161 40.389,151.161 40.659,150.891 JMEDIA.40@40.659,150.141
  other v1: 53.695,139.865
  other v4: 36.2,156.091
  other v5: 36.2,156.091
A_CLK_2_N: D93.4 D93.7 JMEDIA.33 U10_2.18 | length 39.1
  TOP_L1 w0.109: U10_2.18@64.582,139.391 64.757,139.391 64.855,139.489 65.11,139.489 65.21,139.489 65.587,139.865 65.811,140.089 65.901,140.089 65.965,140.025 65.965,139.986 66.021,139.929 v5(66.021,139.891)
  L8 w0.104: v4(45.573,141.397) 45.601,141.369 45.601,141.22 47.311,139.51 60.671,139.51 60.876,139.51 ccw(c60.876,139.943) 61.309,139.943 61.309,140.921 cw(c62.047,140.921) 62.785,140.921 62.785,139.943 ccw(c63.218,139.943) 63.218,139.51 64.237,139.51 64.268,139.541 64.67,139.943 64.67,141.742 65.094,142.166 65.272,142.345 66.53,142.345 67.088,141.787 67.177,141.698 67.177,140.75 66.516,140.089 66.261,140.089 66.063,139.891 v5(66.021,139.891)
  BOTTOM_L10 w0.109: JMEDIA.33@44.469,146.492 44.469,145.742 44.199,145.472 44.082,145.472 44.038,145.427 44.038,145.292 44.134,145.196 44.827,145.196 45.141,144.881 45.141,144.589 45.239,144.491 45.239,143.142 45.141,143.044 45.141,141.691 45.268,141.564 45.395,141.564 ; 45.406,141.564 v4(45.573,141.397)
  other v1: 66.021,139.891
  other v2: 66.021,139.891
  other v3: 45.573,141.397
A_CLK_2_P: D93.5 D93.6 JMEDIA.35 U10_2.19 | length 39.1
  TOP_L1 w0.109: U10_2.19@64.582,139.891 64.757,139.891 64.855,139.793 64.983,139.793 65.084,139.793 65.461,140.17 65.684,140.393 65.901,140.393 65.965,140.457 65.965,140.497 66.021,140.553 v1(66.021,140.591)
  L8 w0.104: v4(45.22,141.044) 45.248,141.016 45.374,141.016 47.184,139.205 47.686,139.205 48.096,139.205 48.168,139.134 48.168,138.989 48.239,138.918 48.454,138.918 48.526,138.989 48.526,139.134 48.597,139.205 50.804,139.205 60.671,139.205 60.876,139.205 ccw(c60.876,139.943) 61.614,139.943 61.614,140.921 cw(c62.047,140.921) 62.48,140.921 62.48,139.943 ccw(c63.218,139.943) 63.218,139.205 64.268,139.205 64.363,139.205 64.974,139.817 64.974,141.616 65.399,142.04 66.404,142.04 66.873,141.572 66.873,140.876 66.39,140.393 66.261,140.393 66.063,140.591 v1(66.021,140.591)
  BOTTOM_L10 w0.109: JMEDIA.35@43.199,146.492 43.199,145.742 43.47,145.472 43.586,145.472 43.733,145.324 43.733,145.165 44.008,144.891 44.701,144.891 44.837,144.755 44.837,144.589 44.739,144.491 D93.6@44.739,144.254 D93.5@44.739,143.379 44.739,143.142 44.837,143.044 44.837,141.565 45.054,141.347 45.054,141.209 v4(45.22,141.044)
  other v2: 66.021,140.591
  other v3: 45.22,141.044
  other v5: 66.021,140.591
A_CLK_3_N: D91.1 D91.10 JMEDIA.3 U10_3.18 | length 43.6
  TOP_L1 w0.109: v3(68.048,145.252) 68.328,145.252 68.991,145.915 69.831,146.756 69.921,146.845 74.02,146.845 74.642,147.466 74.82,147.645 76.291,147.645 76.469,147.466 76.626,147.31 76.804,147.132 76.804,144.065 79.026,141.844 79.081,141.789 82.445,141.789 82.747,141.487 82.747,140.864 82.445,140.562 79.098,140.562 78.975,140.439 78.975,140.068 79.098,139.945 80.711,139.945 81.013,139.643 81.013,139.02 80.711,138.718 80.33,138.718 80.207,138.595 80.207,138.549 80.207,138.279 80.207,138.025 79.727,137.545 77.563,137.545 76.929,138.179 76.929,139.28 76.721,139.489 76.523,139.489 76.496,139.461 76.253,139.461 U10_3.18@76.182,139.391
  BOTTOM_L10 w0.109: JMEDIA.3@63.519,146.492 63.519,145.742 63.249,145.472 63.132,145.472 63.037,145.376 63.037,144.208 63.327,143.918 63.655,143.918 63.753,144.015 D91.10@63.991,144.015 D91.1@64.866,144.015 65.103,144.015 65.201,143.918 66.012,143.918 66.73,144.636 67.712,144.636 68.048,144.973 v3(68.048,145.252)
  other v1: 68.048,145.252
  other v2: 68.048,145.252
  other v4: 68.048,145.252
  other v5: 68.048,145.252
A_CLK_3_P: D91.2 D91.9 JMEDIA.5 U10_3.19 | length 43.5
  TOP_L1 w0.109: v2(68.543,144.757) 68.543,145.037 69.118,145.611 69.958,146.451 70.047,146.54 74.147,146.54 74.947,147.34 76.165,147.34 76.499,147.005 76.499,146.212 76.499,145.794 cw(c76.318,145.794) 76.318,145.613 76.294,145.613 ccw(c76.294,145.431) 76.294,145.249 76.318,145.249 cw(c76.318,145.068) 76.499,145.068 76.499,144.252 76.499,143.939 78.595,141.844 78.9,141.539 78.954,141.484 82.319,141.484 82.442,141.361 82.442,140.99 82.319,140.867 78.972,140.867 78.67,140.565 78.67,139.942 78.972,139.64 80.585,139.64 80.708,139.517 80.708,139.146 80.585,139.023 80.204,139.023 79.902,138.721 79.902,138.549 79.902,138.279 79.902,138.152 79.601,137.85 77.689,137.85 77.234,138.305 77.234,139.407 76.847,139.793 76.523,139.793 76.496,139.821 76.253,139.821 U10_3.19@76.182,139.891
  BOTTOM_L10 w0.109: JMEDIA.5@62.249,146.492 62.249,145.742 62.52,145.472 62.636,145.472 62.732,145.376 62.732,144.082 62.989,143.825 ; 62.994,143.819 63.201,143.613 63.655,143.613 63.753,143.515 D91.9@63.991,143.515 D91.2@64.866,143.515 65.103,143.515 65.201,143.613 66.138,143.613 66.856,144.331 67.838,144.331 68.264,144.757 v2(68.543,144.757)
  other v1: 68.543,144.757
  other v3: 68.543,144.757
  other v4: 68.543,144.757
  other v5: 68.543,144.757
A_LN0_1_N: D97.2 D97.9 JMEDIA.54 U10_1.37 | length 41
  TOP_L1 w0.109: v3(30.899,154.708) 30.899,154.783 31.097,154.981 31.097,155.344 31.453,155.7 32.319,155.7 32.497,155.521 33.048,154.97 33.048,153.406 33.048,152.296 32.757,152.005 31.824,152.005 31.711,151.893 31.711,150.993 31.824,150.88 32.859,150.88 33.15,150.589 33.15,149.436 32.859,149.145 31.715,149.145 31.603,149.033 31.603,148.133 31.715,148.02 32.859,148.02 33.15,147.729 33.15,146.576 32.859,146.285 31.715,146.285 31.603,146.173 31.603,145.273 31.715,145.16 32.757,145.16 33.048,144.869 33.048,144.599 33.048,143.374 33.746,142.676 44.71,142.676 44.985,142.401 44.985,142.132 45.012,142.105 45.012,141.861 U10_1.37@45.082,141.791
  BOTTOM_L10 w0.109: v3(30.899,154.708) 31.097,154.509 31.097,153.589 30.999,153.492 D97.9@30.999,153.254 30.999,152.142 31.097,152.044 31.097,151.752 31.411,151.437 32.104,151.437 32.2,151.341 32.2,151.206 32.156,151.161 32.039,151.161 31.769,150.891 JMEDIA.54@31.769,150.141
  other v1: 30.899,154.708
  other v2: 30.899,154.708
  other v4: 30.899,154.708
  other v5: 30.899,154.708
A_LN0_1_P: D97.1 D97.10 JMEDIA.52 U10_1.38 | length 40.9
  TOP_L1 w0.109: v3(31.599,154.708) 31.599,154.783 31.402,154.981 31.402,155.217 31.579,155.395 32.192,155.395 32.743,154.844 32.743,153.406 32.743,152.423 32.63,152.31 31.698,152.31 31.406,152.019 31.406,150.866 31.698,150.575 32.732,150.575 32.845,150.463 32.845,149.563 32.732,149.45 31.589,149.45 31.298,149.159 31.298,148.006 31.589,147.715 32.732,147.715 32.845,147.603 32.845,146.703 32.732,146.59 31.589,146.59 31.298,146.299 31.298,145.146 31.589,144.855 32.63,144.855 32.743,144.743 32.743,144.599 32.743,143.248 33.62,142.371 34.549,142.371 35.662,142.371 cw(c35.662,142.189) 35.843,142.189 ccw(c36.025,142.189) 36.207,142.189 cw(c36.388,142.189) 36.57,142.189 36.57,142.145 ccw(c36.751,142.145) 36.933,142.145 36.933,142.189 cw(c37.115,142.189) 37.115,142.371 37.169,142.371 44.584,142.371 44.68,142.275 44.68,142.132 44.653,142.105 44.653,141.861 U10_1.38@44.582,141.791
  BOTTOM_L10 w0.109: v3(31.599,154.708) 31.402,154.509 31.402,153.589 31.499,153.492 D97.10@31.499,153.254 D97.1@31.499,152.379 31.499,152.142 31.401,152.044 31.401,151.878 31.537,151.742 32.23,151.742 32.505,151.468 32.505,151.308 32.652,151.161 32.769,151.161 33.039,150.891 JMEDIA.52@33.039,150.141
  other v1: 31.599,154.708
  other v2: 31.599,154.708
  other v4: 31.599,154.708
  other v5: 31.599,154.708
A_LN0_2_N: D92.4 D92.7 JMEDIA.21 U10_2.37 | length 38.8
  TOP_L1 w0.109: v5(56.56,142.84) 56.56,142.802 56.453,142.695 56.453,142.538 56.585,142.406 56.585,142.132 56.612,142.105 56.612,141.861 U10_2.37@56.682,141.791
  L8 w0.104: v3(52.959,142.54) 52.762,142.738 52.762,150.235 53.241,150.715 53.842,150.715 54.313,150.244 54.313,148.092 55.105,147.3 60.526,147.3 60.901,146.925 60.901,145.828 60.625,145.551 55.32,145.551 54.366,144.597 54.366,142.542 54.848,142.06 55.172,141.735 55.784,141.735 56.362,142.314 56.362,142.749 56.454,142.84 v5(56.56,142.84)
  BOTTOM_L10 w0.109: JMEDIA.21@52.089,146.492 52.089,145.742 51.819,145.472 51.702,145.472 51.658,145.427 51.658,145.292 51.754,145.196 52.447,145.196 52.761,144.881 52.761,144.589 52.859,144.491 D92.4@52.859,143.379 ; D92.4@52.859,143.379 52.859,143.141 52.762,143.044 52.762,142.738 v3(52.959,142.54)
  other v1: 56.56,142.84
  other v2: 56.56,142.84
  other v4: 52.959,142.54
A_LN0_2_P: D92.5 D92.6 JMEDIA.23 U10_2.38 | length 38.9
  TOP_L1 w0.109: v5(55.86,142.84) 56.148,142.552 56.148,142.412 56.28,142.28 56.28,142.132 56.253,142.105 56.253,141.861 U10_2.38@56.182,141.791
  L8 w0.104: v4(52.259,142.54) 52.457,142.738 52.457,150.361 53.115,151.02 53.968,151.02 54.618,150.37 54.618,148.219 54.93,147.907 55.036,147.8 55.232,147.605 60.653,147.605 61.206,147.051 61.206,145.701 60.751,145.246 55.446,145.246 54.671,144.471 54.671,142.668 55.299,142.04 55.658,142.04 56.058,142.44 56.058,142.749 55.966,142.84 v5(55.86,142.84)
  BOTTOM_L10 w0.109: JMEDIA.23@50.819,146.492 50.819,145.742 51.09,145.472 51.206,145.472 51.353,145.324 51.353,145.165 51.628,144.891 52.321,144.891 52.457,144.755 52.457,144.589 52.359,144.491 D92.5@52.359,143.379 ; v4(52.259,142.54) 52.457,142.738 52.457,143.044 52.359,143.141 D92.5@52.359,143.379
  other v1: 55.86,142.84
  other v2: 55.86,142.84
  other v3: 52.259,142.54
A_LN0_3_N: D90.1 D90.10 JMEDIA.12 U10_3.37 | length 43.6
  TOP_L1 w0.109: v5(68.067,142.848) 68.04,142.821 68.04,142.722 68.017,142.698 68.017,142.259 68.212,142.064 68.212,141.861 U10_3.37@68.282,141.791
  BOTTOM_L10 w0.109: JMEDIA.12@58.439,150.141 58.439,150.891 58.71,151.161 58.826,151.161 58.973,151.308 58.973,151.468 59.248,151.742 59.941,151.742 60.077,151.878 60.077,152.044 59.979,152.142 D90.1@59.979,153.254 59.979,153.492 60.077,153.589 60.077,153.805 60.077,154.013 ccw(c59.768,154.012) 59.768,154.321 58.13,154.321 cw(c58.13,154.934) 58.13,155.548 59.768,155.548 ccw(c59.768,155.856) 60.077,155.856 60.077,156.564 60.077,156.633 60.255,156.812 60.388,156.944 60.566,157.123 65.966,157.123 67.871,155.217 67.871,151.695 69.183,150.384 72.9,150.384 73.563,149.721 73.741,149.543 73.741,146.601 73.247,146.107 73.247,144.952 72.684,144.389 69.851,144.389 68.766,143.305 67.999,143.305 67.903,143.209 67.903,143.073 67.997,142.979 67.997,142.957 68.067,142.887 v5(68.067,142.848)
  other v1: 68.067,142.848
  other v2: 68.067,142.848
  other v3: 68.067,142.848
  other v4: 68.067,142.848
A_LN0_3_P: D90.2 D90.9 JMEDIA.10 U10_3.38 | length 43.6
  TOP_L1 w0.109: v4(67.367,142.848) 67.399,142.848 67.712,142.535 67.712,141.861 U10_3.38@67.782,141.791
  BOTTOM_L10 w0.109: JMEDIA.10@59.709,150.141 59.709,150.891 59.439,151.161 59.322,151.161 59.278,151.206 59.278,151.341 59.374,151.437 60.067,151.437 60.381,151.752 60.381,152.044 60.479,152.142 D90.2@60.479,153.254 60.479,153.492 60.382,153.589 60.382,153.805 60.382,153.905 60.382,154.012 ccw(c59.768,154.012) 59.768,154.626 58.13,154.626 cw(c58.13,154.934) 58.13,155.243 59.768,155.243 ccw(c59.768,155.856) 60.382,155.856 60.382,156.507 60.439,156.564 60.692,156.818 60.802,156.818 61.22,156.818 cw(c61.22,156.636) 61.401,156.636 61.401,156.593 ccw(c61.583,156.593) 61.765,156.593 61.765,156.636 cw(c61.946,156.636) 62.128,156.636 ccw(c62.309,156.636) 62.491,156.636 cw(c62.673,156.636) 62.673,156.818 63,156.818 65.84,156.818 67.567,155.091 67.567,151.569 69.057,150.079 72.774,150.079 73.436,149.416 73.436,146.727 72.942,146.233 72.942,145.078 72.558,144.694 69.724,144.694 68.64,143.609 67.873,143.609 67.598,143.335 67.598,143.079 v4(67.367,142.848)
  other v1: 67.367,142.848
  other v2: 67.367,142.848
  other v3: 67.367,142.848
  other v5: 67.367,142.848
A_LN1_1_N: D96.5 D96.6 JMEDIA.48 U10_1.35 | length 41
  TOP_L1 w0.109: v1(34.9,153.065) 34.846,153.011 34.567,153.011 34.33,152.774 34.33,152.085 34.33,151.942 34.461,151.811 35.857,151.811 36.167,151.502 36.167,150.639 35.857,150.33 34.403,150.33 34.273,150.199 34.273,149.589 34.403,149.459 35.857,149.459 36.167,149.15 36.167,148.287 35.857,147.978 34.403,147.978 34.273,147.847 34.273,147.237 34.403,147.107 35.834,147.107 36.144,146.798 36.144,145.935 35.834,145.626 34.461,145.626 34.33,145.495 34.33,144.782 34.33,144.039 34.66,143.708 35.699,143.708 36.475,143.708 ccw(c36.475,143.89) 36.656,143.89 36.656,144.141 cw(c36.838,144.141) 37.02,144.141 37.02,143.89 ccw(c37.201,143.89) 37.201,143.708 37.619,143.708 44.887,143.708 44.939,143.656 45.806,142.79 45.985,142.611 45.985,142.132 46.012,142.105 46.012,141.861 U10_1.35@46.082,141.791
  BOTTOM_L10 w0.109: v1(34.9,153.065) 34.901,153.345 35.539,153.983 37.121,153.983 37.217,153.887 37.217,153.589 37.119,153.492 D96.6@37.119,153.254 37.119,152.142 37.217,152.044 37.217,151.878 37.081,151.742 36.388,151.742 36.113,151.468 36.113,151.308 35.966,151.161 35.85,151.161 35.579,150.891 JMEDIA.48@35.579,150.141
  other v2: 34.9,153.065
  other v3: 34.9,153.065
  other v4: 34.9,153.065
  other v5: 34.9,153.065
A_LN1_1_P: D96.4 D96.7 JMEDIA.46 U10_1.36 | length 41
  TOP_L1 w0.109: v1(34.405,153.56) 34.351,153.506 34.351,153.227 34.025,152.901 34.025,152.085 34.025,151.815 34.334,151.506 35.731,151.506 35.862,151.375 35.862,150.765 35.731,150.635 34.277,150.635 33.968,150.326 33.968,149.463 34.277,149.154 35.731,149.154 35.862,149.023 35.862,148.413 35.731,148.283 34.277,148.283 33.968,147.974 33.968,147.111 34.277,146.802 35.708,146.802 35.839,146.671 35.839,146.061 35.708,145.931 34.334,145.931 34.025,145.622 34.025,144.782 34.025,143.912 34.534,143.403 44.761,143.403 44.813,143.351 45.68,142.485 45.68,142.132 45.653,142.105 45.653,141.861 U10_1.36@45.582,141.791
  BOTTOM_L10 w0.109: v1(34.405,153.56) 34.685,153.561 35.413,154.288 37.247,154.288 37.521,154.014 37.521,153.589 37.619,153.492 D96.7@37.619,153.254 D96.4@37.619,152.379 37.619,152.142 37.521,152.044 37.521,151.752 37.207,151.437 36.514,151.437 36.418,151.341 36.418,151.206 36.462,151.161 36.579,151.161 36.849,150.891 JMEDIA.46@36.849,150.141
  other v2: 34.405,153.56
  other v3: 34.405,153.56
  other v4: 34.405,153.56
  other v5: 34.405,153.56
A_LN1_2_N: D93.1 D93.10 JMEDIA.27 U10_2.35 | length 39.1
  TOP_L1 w0.109: U10_2.35@57.682,141.791 57.612,141.861 57.612,142.105 57.585,142.132 57.585,143.199 57.782,143.396 v5(57.782,143.44)
  L8 w0.104: v4(48.104,141.64) 47.907,141.443 47.651,141.443 47.381,141.172 47.381,140.512 47.757,140.135 49.036,140.135 49.304,140.135 49.706,140.538 49.706,148.072 49.931,148.296 50.603,148.296 50.827,148.072 50.827,140.538 51.229,140.135 51.523,140.135 56.03,140.135 57.585,141.689 57.585,143.201 57.782,143.398 v5(57.782,143.44)
  BOTTOM_L10 w0.109: v4(48.104,141.64) 47.907,141.443 47.476,141.443 46.641,142.277 46.641,143.044 46.739,143.142 D93.10@46.739,144.254 46.739,144.491 46.641,144.589 46.641,144.755 46.777,144.891 47.47,144.891 47.745,145.165 47.745,145.324 47.892,145.472 48.009,145.472 48.279,145.742 JMEDIA.27@48.279,146.492
  other v1: 57.782,143.44
  other v2: 57.782,143.44
  other v3: 48.104,141.64
A_LN1_2_P: D93.2 D93.9 JMEDIA.29 U10_2.36 | length 39.1
  TOP_L1 w0.109: v5(57.082,143.44) 57.082,143.396 57.28,143.199 57.28,142.132 57.253,142.105 57.253,141.861 U10_2.36@57.182,141.791
  L8 w0.104: v4(48.104,140.94) 47.907,141.138 47.777,141.138 47.686,141.046 47.686,140.638 47.884,140.44 49.036,140.44 49.178,140.44 49.402,140.664 49.402,148.198 49.804,148.601 50.729,148.601 51.131,148.198 51.131,140.664 51.355,140.44 51.523,140.44 52.86,140.44 52.912,140.44 ccw(c52.912,140.619) 53.091,140.619 53.091,140.712 cw(c53.271,140.712) 53.45,140.712 53.45,140.619 ccw(c53.629,140.619) 53.808,140.619 cw(c53.987,140.619) 54.166,140.619 ccw(c54.345,140.619) 54.345,140.44 55.371,140.44 55.904,140.44 57.28,141.816 57.28,143.201 57.082,143.398 v5(57.082,143.44)
  BOTTOM_L10 w0.109: JMEDIA.29@47.009,146.492 47.009,145.742 47.279,145.472 47.396,145.472 47.44,145.427 47.44,145.292 47.344,145.196 46.651,145.196 46.337,144.881 46.337,144.589 46.239,144.491 D93.9@46.239,144.254 D93.2@46.239,143.379 46.239,143.142 46.337,143.044 46.337,142.151 47.35,141.138 47.907,141.138 v4(48.104,140.94)
  other v1: 57.082,143.44
  other v2: 57.082,143.44
  other v3: 48.104,140.94
A_LN1_3_N: D90.4 D90.7 JMEDIA.6 U10_3.35 | length 43.6
  TOP_L1 w0.109: U10_3.35@69.282,141.791 69.212,141.861 69.212,142.105 69.185,142.132 69.185,143.761 70.423,144.999 71.284,144.999 71.525,145.24 v1(71.804,145.24)
  BOTTOM_L10 w0.109: JMEDIA.6@62.249,150.141 62.249,150.891 62.519,151.161 62.636,151.161 62.68,151.206 62.68,151.341 62.584,151.437 61.891,151.437 61.577,151.752 61.577,152.044 61.479,152.142 D90.4@61.479,153.254 61.479,153.492 61.577,153.589 61.577,154.166 62.155,154.745 62.348,154.745 63.158,154.745 63.251,154.838 63.251,155.807 63.522,156.078 64.206,156.078 64.477,155.807 64.477,152.517 64.57,152.425 65.002,152.425 65.095,152.517 65.095,154.474 65.366,154.745 65.636,154.745 65.924,154.745 66.409,154.26 66.409,148.308 66.715,148.002 66.985,147.732 67.159,147.732 67.283,147.856 67.283,149.078 67.585,149.38 68.208,149.38 68.509,149.078 68.509,146.822 68.633,146.699 69.003,146.699 69.127,146.822 69.127,148.655 69.429,148.957 70.052,148.957 70.354,148.655 70.354,146.964 70.477,146.84 71.577,146.84 71.735,146.84 71.914,146.662 72.181,146.394 72.181,145.886 71.835,145.54 71.835,145.371 71.831,145.367 71.831,145.267 v1(71.804,145.24)
  other v2: 71.804,145.24
  other v3: 71.804,145.24
  other v4: 71.804,145.24
  other v5: 71.804,145.24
